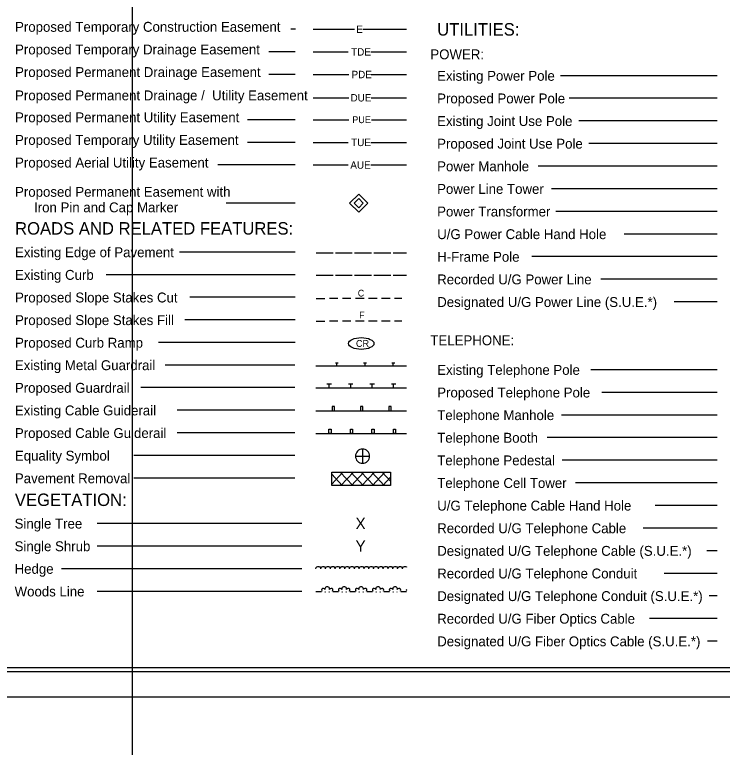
# Model space of a CAD drawing. Extents: x 572269 to 579912, y -56875 to -49627.
# Drawn here: x 574480 to 575106, y -52186 to -51539 of the extents above; entities that cross this region are included whole.
import ezdxf

# ---------------------------------------------------------------- set-up
doc = ezdxf.new("R2010")
doc.units = 0
for name, color, linetype in [('Default', 7, 'Continuous'), ('Prop Easement Permanent Drainage Utility', 7, 'Continuous'), ('Prop VPI Label', 7, 'Continuous'), ('Scratch_Level_3', 7, 'Continuous'), ('Sheet Cutting Line CELL', 7, 'Continuous'), ('Sheet Plot Border Inside CELL', 7, 'Continuous'), ('Sheet Plot Border Outside CELL', 7, 'Continuous'), ('Sheet Symbology CELL', 7, 'Continuous')]:
    doc.layers.add(name, color=color, linetype=linetype)

# ---------------------------------------------------------------- blocks, each defined once
blk = doc.blocks.new('EQCIR')
at = {"layer": 'Sheet Symbology CELL'}
for p, q in [((-0.25, 0), (0, 0)), ((0, 0.25), (0, 0)), ((0, 0), (0, -0.25)), ((0, 0), (0.25, 0))]:
    blk.add_line(p, q, dxfattribs=at)
for start, end in [(89.9944, 179.9989), (359.9944, 89.9989), (179.9944, 269.9989), (269.9944, 359.9989)]:
    blk.add_arc((0, 0), 0.25, start, end, dxfattribs=at)
blk = doc.blocks.new('ROW Marker Permanent Easement-E')
at = {"layer": 'Prop ROW Permanent Easement CELL'}
blk.add_line((0, 0), (0, 0), dxfattribs=at)
for points in [[(0, 0.072), (0.072, 0), (0, -0.072), (-0.072, 0)], [(0, 0.036), (0.036, 0), (0, -0.036), (-0.036, 0)]]:
    blk.add_lwpolyline(points, close=True, dxfattribs=at)
blk = doc.blocks.new('CR')
at = {"layer": 'Prop WCC CELL'}
blk.add_ellipse((0.02, -0.02), major_axis=(5.61, 0), ratio=0.462467, dxfattribs=at)
blk.add_text('CR', height=3, dxfattribs=at).set_placement((-2.34, -1.5))
blk = doc.blocks.new('PLAN SHEET SYMBOLOGY')
at = {"layer": 'Prop Easement Permanent Drainage Utility'}
for p, q in [((16.51, 10.596), (17.136, 10.596)), ((17.536, 10.596), (18.16, 10.596))]:
    blk.add_line(p, q, dxfattribs=at)
at = {"layer": 'Sheet Cutting Line CELL'}
blk.add_line((0, 0), (33.68, 0), dxfattribs=at)
at = {"layer": 'Sheet Plot Border Inside CELL'}
blk.add_lwpolyline([(0.26, 0.449), (33.59, 0.449), (33.59, 21.551), (0.26, 21.551)], close=True, dxfattribs=at)
at = {"layer": 'Sheet Plot Border Outside CELL'}
blk.add_lwpolyline([(0, 0), (33.68, 0), (33.68, 22), (0, 22)], close=True, dxfattribs=at)
at = {"layer": 'Sheet Symbology CELL'}
for p, q in [((16.197, 11.807), (16.114, 11.807)), ((16.51, 11.807), (16.562, 11.807)), ((16.562, 11.807), (17.237, 11.807)), ((17.387, 11.807), (18.062, 11.807)), ((18.062, 11.807), (18.16, 11.807)), ((16.189, 11.407), (15.726, 11.407)), ((16.51, 11.407), (16.577, 11.407)), ((16.577, 11.407), (17.127, 11.407)), ((17.527, 11.407), (18.077, 11.407)), ((18.077, 11.407), (18.16, 11.407)), ((16.189, 11.007), (15.726, 11.007)), ((16.51, 11.007), (16.586, 11.007)), ((16.586, 11.007), (17.136, 11.007)), ((17.536, 11.007), (18.086, 11.007)), ((18.086, 11.007), (18.16, 11.007)), ((23.656, 10.986), (20.882, 10.986)), ((23.656, 10.586), (21.038, 10.586)), ((16.189, 10.207), (15.347, 10.207)), ((16.51, 10.207), (16.587, 10.207)), ((16.587, 10.207), (17.137, 10.207)), ((17.537, 10.207), (18.087, 10.207)), ((18.087, 10.207), (18.16, 10.207)), ((23.656, 10.186), (21.206, 10.186)), ((16.189, 9.807), (15.347, 9.807)), ((16.51, 9.807), (16.577, 9.807)), ((16.577, 9.807), (17.127, 9.807)), ((17.527, 9.807), (18.077, 9.807)), ((18.077, 9.807), (18.16, 9.807)), ((23.656, 9.786), (21.386, 9.786)), ((16.189, 9.407), (14.82, 9.407)), ((16.51, 9.407), (16.577, 9.407)), ((16.577, 9.407), (17.127, 9.407)), ((17.527, 9.407), (18.077, 9.407)), ((18.077, 9.407), (18.16, 9.407)), ((23.656, 9.386), (20.486, 9.386)), ((23.656, 8.986), (20.726, 8.986)), ((16.189, 8.731), (14.969, 8.731)), ((23.656, 8.586), (20.798, 8.586)), ((23.656, 8.186), (22.009, 8.186)), ((16.189, 7.867), (14.142, 7.867)), ((16.56, 7.856), (16.86, 7.856)), ((16.9, 7.856), (17.2, 7.856)), ((17.24, 7.856), (17.54, 7.856)), ((17.58, 7.856), (17.88, 7.856)), ((17.92, 7.856), (18.16, 7.856)), ((23.656, 7.786), (20.378, 7.786)), ((16.189, 7.467), (12.846, 7.467)), ((16.56, 7.456), (16.86, 7.456)), ((16.9, 7.456), (17.2, 7.456)), ((17.24, 7.456), (17.54, 7.456)), ((17.58, 7.456), (17.88, 7.456)), ((17.92, 7.456), (18.16, 7.456)), ((23.656, 7.386), (21.597, 7.386)), ((16.189, 7.067), (14.326, 7.067)), ((16.56, 7.046), (16.712, 7.046)), ((16.946, 7.046), (16.795, 7.046)), ((17.176, 7.046), (17.024, 7.046)), ((17.411, 7.046), (17.255, 7.046)), ((17.64, 7.046), (17.485, 7.046)), ((17.871, 7.046), (17.714, 7.046)), ((18.077, 7.046), (17.949, 7.046)), ((23.656, 6.986), (22.892, 6.986)), ((16.189, 6.667), (14.235, 6.667)), ((16.56, 6.646), (16.712, 6.646)), ((16.946, 6.646), (16.795, 6.646)), ((17.176, 6.646), (17.024, 6.646)), ((17.411, 6.646), (17.255, 6.646)), ((17.64, 6.646), (17.485, 6.646)), ((17.871, 6.646), (17.714, 6.646)), ((18.077, 6.646), (17.949, 6.646)), ((16.189, 6.267), (13.771, 6.267)), ((16.186, 5.87), (13.889, 5.87)), ((16.557, 5.858), (18.157, 5.858)), ((16.9, 5.908), (16.95, 5.908)), ((16.925, 5.858), (16.925, 5.908)), ((17.4, 5.908), (17.45, 5.908)), ((17.425, 5.858), (17.425, 5.908)), ((17.9, 5.908), (17.95, 5.908)), ((17.925, 5.858), (17.925, 5.908)), ((23.656, 5.786), (21.418, 5.786)), ((16.186, 5.47), (13.461, 5.47)), ((18.157, 5.458), (16.557, 5.458)), ((16.751, 5.537), (16.831, 5.537)), ((16.791, 5.458), (16.791, 5.537)), ((17.131, 5.537), (17.211, 5.537)), ((17.171, 5.458), (17.171, 5.537)), ((17.511, 5.537), (17.591, 5.537)), ((17.551, 5.458), (17.551, 5.537)), ((17.891, 5.537), (17.971, 5.537)), ((17.931, 5.458), (17.931, 5.537)), ((23.656, 5.386), (21.615, 5.386)), ((16.186, 5.07), (14.1, 5.07)), ((16.557, 5.058), (18.157, 5.058)), ((23.656, 4.986), (20.899, 4.986)), ((16.186, 4.67), (14.1, 4.67)), ((16.557, 4.658), (18.157, 4.658)), ((23.656, 4.586), (20.646, 4.586)), ((16.186, 4.27), (13.334, 4.27)), ((23.656, 4.186), (20.913, 4.186)), ((16.836, 3.976), (17.878, 3.976)), ((16.836, 3.742), (16.836, 3.976)), ((16.836, 3.964), (16.847, 3.976)), ((16.836, 3.765), (17.033, 3.976)), ((17.021, 3.742), (16.836, 3.94)), ((17.207, 3.742), (16.987, 3.976)), ((16.999, 3.742), (17.219, 3.976)), ((17.392, 3.742), (17.173, 3.976)), ((17.184, 3.742), (17.405, 3.976)), ((17.578, 3.742), (17.358, 3.976)), ((17.37, 3.742), (17.59, 3.976)), ((17.764, 3.742), (17.543, 3.976)), ((17.556, 3.742), (17.775, 3.976)), ((17.878, 3.817), (17.729, 3.976)), ((17.741, 3.742), (17.878, 3.888)), ((17.878, 3.976), (17.878, 3.742)), ((16.186, 3.87), (13.334, 3.87)), ((23.656, 3.786), (21.151, 3.786)), ((17.878, 3.742), (16.836, 3.742)), ((23.656, 3.386), (22.555, 3.386)), ((16.309, 3.068), (12.686, 3.068)), ((23.656, 2.986), (22.345, 2.986)), ((16.309, 2.668), (12.686, 2.668)), ((23.656, 2.586), (23.473, 2.586)), ((16.309, 2.268), (12.055, 2.268)), ((16.557, 2.268), (16.563, 2.287)), ((16.563, 2.287), (16.575, 2.3)), ((16.575, 2.3), (16.591, 2.309)), ((16.591, 2.309), (16.61, 2.309)), ((16.61, 2.309), (16.626, 2.299)), ((16.626, 2.299), (16.637, 2.286)), ((16.637, 2.286), (16.641, 2.269)), ((16.642, 2.268), (16.648, 2.287)), ((16.648, 2.287), (16.66, 2.3)), ((16.66, 2.3), (16.676, 2.309)), ((16.676, 2.309), (16.695, 2.309)), ((16.695, 2.309), (16.711, 2.299)), ((16.711, 2.299), (16.722, 2.286)), ((16.722, 2.286), (16.726, 2.269)), ((16.727, 2.268), (16.733, 2.287)), ((16.733, 2.287), (16.745, 2.3)), ((16.745, 2.3), (16.761, 2.309)), ((16.761, 2.309), (16.78, 2.309)), ((16.78, 2.309), (16.796, 2.299)), ((16.796, 2.299), (16.807, 2.286)), ((16.807, 2.286), (16.811, 2.269)), ((16.812, 2.268), (16.818, 2.287)), ((16.818, 2.287), (16.83, 2.3)), ((16.83, 2.3), (16.846, 2.309)), ((16.846, 2.309), (16.865, 2.309)), ((16.865, 2.309), (16.881, 2.299)), ((16.881, 2.299), (16.892, 2.286)), ((16.892, 2.286), (16.896, 2.269)), ((16.897, 2.268), (16.903, 2.287)), ((16.903, 2.287), (16.915, 2.3)), ((16.915, 2.3), (16.931, 2.309)), ((16.931, 2.309), (16.95, 2.309)), ((16.95, 2.309), (16.966, 2.299)), ((16.966, 2.299), (16.977, 2.286)), ((16.977, 2.286), (16.981, 2.269)), ((16.982, 2.268), (16.988, 2.287)), ((16.988, 2.287), (17, 2.3)), ((17, 2.3), (17.016, 2.309)), ((17.016, 2.309), (17.035, 2.309)), ((17.035, 2.309), (17.051, 2.299)), ((17.051, 2.299), (17.062, 2.286)), ((17.062, 2.286), (17.066, 2.269)), ((17.067, 2.268), (17.073, 2.287)), ((17.073, 2.287), (17.085, 2.3)), ((17.085, 2.3), (17.101, 2.309)), ((17.101, 2.309), (17.12, 2.309)), ((17.12, 2.309), (17.136, 2.299)), ((17.136, 2.299), (17.147, 2.286)), ((17.147, 2.286), (17.151, 2.269)), ((17.152, 2.268), (17.158, 2.287)), ((17.158, 2.287), (17.17, 2.3)), ((17.17, 2.3), (17.186, 2.309)), ((17.186, 2.309), (17.205, 2.309)), ((17.205, 2.309), (17.221, 2.299)), ((17.221, 2.299), (17.232, 2.286)), ((17.232, 2.286), (17.236, 2.269)), ((17.237, 2.268), (17.243, 2.287)), ((17.243, 2.287), (17.255, 2.3)), ((17.255, 2.3), (17.271, 2.309)), ((17.271, 2.309), (17.29, 2.309)), ((17.29, 2.309), (17.306, 2.299)), ((17.306, 2.299), (17.317, 2.286)), ((17.317, 2.286), (17.321, 2.269)), ((17.322, 2.268), (17.328, 2.287)), ((17.328, 2.287), (17.34, 2.3)), ((17.34, 2.3), (17.356, 2.309)), ((17.356, 2.309), (17.375, 2.309)), ((17.375, 2.309), (17.391, 2.299)), ((17.391, 2.299), (17.402, 2.286)), ((17.402, 2.286), (17.406, 2.269)), ((17.407, 2.268), (17.413, 2.287)), ((17.413, 2.287), (17.425, 2.3)), ((17.425, 2.3), (17.441, 2.309)), ((17.441, 2.309), (17.46, 2.309)), ((17.46, 2.309), (17.476, 2.299)), ((17.476, 2.299), (17.487, 2.286)), ((17.487, 2.286), (17.491, 2.269)), ((17.492, 2.268), (17.498, 2.287)), ((17.498, 2.287), (17.51, 2.3)), ((17.51, 2.3), (17.526, 2.309)), ((17.526, 2.309), (17.545, 2.309)), ((17.545, 2.309), (17.561, 2.299)), ((17.561, 2.299), (17.572, 2.286)), ((17.572, 2.286), (17.576, 2.269)), ((17.577, 2.268), (17.583, 2.287)), ((17.583, 2.287), (17.595, 2.3)), ((17.595, 2.3), (17.611, 2.309)), ((17.611, 2.309), (17.63, 2.309)), ((17.63, 2.309), (17.646, 2.299)), ((17.646, 2.299), (17.657, 2.286)), ((17.657, 2.286), (17.661, 2.269)), ((17.662, 2.268), (17.668, 2.287)), ((17.668, 2.287), (17.68, 2.3)), ((17.68, 2.3), (17.696, 2.309)), ((17.696, 2.309), (17.715, 2.309)), ((17.715, 2.309), (17.731, 2.299)), ((17.731, 2.299), (17.742, 2.286)), ((17.742, 2.286), (17.746, 2.269)), ((17.747, 2.268), (17.753, 2.287)), ((17.753, 2.287), (17.765, 2.3)), ((17.765, 2.3), (17.781, 2.309)), ((17.781, 2.309), (17.8, 2.309)), ((17.8, 2.309), (17.816, 2.299)), ((17.816, 2.299), (17.827, 2.286)), ((17.827, 2.286), (17.831, 2.269)), ((17.832, 2.268), (17.838, 2.287)), ((17.838, 2.287), (17.85, 2.3)), ((17.85, 2.3), (17.866, 2.309)), ((17.866, 2.309), (17.885, 2.309)), ((17.885, 2.309), (17.901, 2.299)), ((17.901, 2.299), (17.912, 2.286)), ((17.912, 2.286), (17.916, 2.269)), ((17.917, 2.268), (17.923, 2.287)), ((17.923, 2.287), (17.935, 2.3)), ((17.935, 2.3), (17.951, 2.309)), ((17.951, 2.309), (17.97, 2.309)), ((17.97, 2.309), (17.986, 2.299)), ((17.986, 2.299), (17.997, 2.286)), ((17.997, 2.286), (18.001, 2.269)), ((18.002, 2.268), (18.008, 2.287)), ((18.008, 2.287), (18.02, 2.3)), ((18.02, 2.3), (18.036, 2.309)), ((18.036, 2.309), (18.055, 2.309)), ((18.055, 2.309), (18.071, 2.299)), ((18.071, 2.299), (18.082, 2.286)), ((18.082, 2.286), (18.086, 2.269)), ((18.087, 2.268), (18.093, 2.287)), ((18.093, 2.287), (18.105, 2.3)), ((18.105, 2.3), (18.121, 2.309)), ((18.121, 2.309), (18.14, 2.309)), ((18.14, 2.309), (18.156, 2.299)), ((18.156, 2.299), (18.157, 2.298)), ((23.656, 2.186), (22.717, 2.186)), ((16.309, 1.868), (12.686, 1.868)), ((16.557, 1.868), (16.657, 1.868)), ((16.716, 1.858), (16.726, 1.858)), ((16.786, 1.858), (16.796, 1.858)), ((16.857, 1.868), (16.957, 1.868)), ((17.016, 1.858), (17.026, 1.858)), ((17.086, 1.858), (17.096, 1.858)), ((17.157, 1.868), (17.257, 1.868)), ((17.316, 1.858), (17.326, 1.858)), ((17.386, 1.858), (17.396, 1.858)), ((17.457, 1.868), (17.557, 1.868)), ((17.616, 1.858), (17.626, 1.858)), ((17.686, 1.858), (17.696, 1.858)), ((17.757, 1.868), (17.857, 1.868)), ((17.916, 1.858), (17.926, 1.858)), ((17.986, 1.858), (17.996, 1.858)), ((18.057, 1.868), (18.157, 1.868)), ((23.656, 1.786), (23.515, 1.786)), ((23.656, 1.386), (22.455, 1.386)), ((23.656, 0.986), (23.485, 0.986))]:
    blk.add_line(p, q, dxfattribs=at)
for points in [[(33.34, 21.5), (3.34, 21.5), (3.34, 0.52), (33.34, 0.52)], [(16.846, 5.058), (16.886, 5.058), (16.886, 5.138), (16.846, 5.138)], [(17.346, 5.058), (17.386, 5.058), (17.386, 5.138), (17.346, 5.138)], [(17.846, 5.058), (17.886, 5.058), (17.886, 5.138), (17.846, 5.138)], [(16.786, 4.738), (16.826, 4.738), (16.826, 4.658), (16.786, 4.658)], [(17.166, 4.738), (17.206, 4.738), (17.206, 4.658), (17.166, 4.658)], [(17.546, 4.738), (17.586, 4.738), (17.586, 4.658), (17.546, 4.658)], [(17.926, 4.738), (17.966, 4.738), (17.966, 4.658), (17.926, 4.658)]]:
    blk.add_lwpolyline(points, close=True, dxfattribs=at)
for centre, radius, start, end in [((16.756, 1.909), 0.0412, 345.9638, 194.0362), ((17.056, 1.909), 0.0412, 345.9638, 194.0362), ((17.356, 1.909), 0.0412, 345.9638, 194.0362), ((17.656, 1.909), 0.0412, 345.9638, 194.0362), ((17.956, 1.909), 0.0412, 345.9638, 194.0362), ((16.686, 1.889), 0.0316, 18.435, 219.2315), ((16.826, 1.889), 0.0316, 320.7685, 161.5651), ((16.986, 1.889), 0.0316, 18.435, 219.2315), ((17.126, 1.889), 0.0316, 320.7685, 161.5651), ((17.286, 1.889), 0.0316, 18.435, 219.2315), ((17.426, 1.889), 0.0316, 320.7685, 161.5651), ((17.586, 1.889), 0.0316, 18.435, 219.2315), ((17.726, 1.889), 0.0316, 320.7685, 161.5651), ((17.886, 1.889), 0.0316, 18.435, 219.2315), ((18.026, 1.889), 0.0316, 320.7685, 161.5651), ((18.186, 1.889), 0.0316, 156.251, 203.749)]:
    blk.add_arc(centre, radius, start, end, dxfattribs=at)
at = {"layer": 'Default', "xscale": 0.5, "yscale": 0.5}
blk.add_blockref('EQCIR', (17.381, 4.258), dxfattribs=at)
at = {"layer": 'Sheet Symbology CELL'}
for name, p, xscale, yscale in [('ROW Marker Permanent Easement-E', (17.313, 8.731), 2.2367546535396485, 2.2367546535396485), ('CR', (17.358, 6.251), 0.04, 0.04)]:
    blk.add_blockref(name, p, dxfattribs=dict(at, xscale=xscale, yscale=yscale))
at = {"layer": 'Prop Easement Permanent Drainage Utility'}
blk.add_text('DUE', height=0.131, dxfattribs=at).set_placement((17.168, 10.53))
at = {"layer": 'Sheet Symbology CELL'}
for s, height, p in [('Proposed Temporary Construction Easement', 0.175, (11.234, 11.762)), ('E', 0.131, (17.269, 11.741)), ('UTILITIES:', 0.22, (18.701, 11.695)), ('Proposed Temporary Drainage Easement', 0.175, (11.234, 11.362)), ('TDE', 0.131, (17.179, 11.341)), ('POWER:', 0.175, (18.581, 11.276)), ('Proposed Permanent Drainage Easement', 0.175, (11.234, 10.962)), ('PDE', 0.131, (17.186, 10.941)), ('Existing Power Pole', 0.175, (18.701, 10.896)), ('Proposed Permanent Drainage /  Utility Easement', 0.175, (11.234, 10.55)), ('Proposed Power Pole', 0.175, (18.701, 10.496)), ('Proposed Permanent Utility Easement', 0.175, (11.234, 10.162)), ('PUE', 0.12, (17.199, 10.147)), ('Existing Joint Use Pole', 0.175, (18.701, 10.096)), ('Proposed Temporary Utility Easement', 0.175, (11.234, 9.762)), ('TUE', 0.131, (17.179, 9.741)), ('Proposed Joint Use Pole', 0.175, (18.701, 9.696)), ('Proposed Aerial Utility Easement', 0.175, (11.234, 9.362)), ('AUE', 0.131, (17.165, 9.341)), ('Power Manhole', 0.175, (18.701, 9.296)), ('Power Line Tower', 0.175, (18.701, 8.896)), ('Proposed Permanent Easement with', 0.175, (11.234, 8.845)), ('Iron Pin and Cap Marker', 0.175, (11.57, 8.57)), ('Power Transformer', 0.175, (18.701, 8.496)), ('ROADS AND RELATED FEATURES:', 0.22, (11.234, 8.176)), ('U/G Power Cable Hand Hole', 0.175, (18.702, 8.096)), ('Existing Edge of Pavement', 0.175, (11.234, 7.776)), ('H-Frame Pole', 0.175, (18.702, 7.696)), ('Existing Curb', 0.175, (11.234, 7.376)), ('Recorded U/G Power Line', 0.175, (18.702, 7.296)), ('Proposed Slope Stakes Cut', 0.175, (11.234, 6.976)), ('C', 0.119, (17.296, 7.081)), ('Designated U/G Power Line (S.U.E.*)', 0.175, (18.702, 6.896)), ('Proposed Slope Stakes Fill', 0.175, (11.234, 6.576)), ('F', 0.119, (17.32, 6.694)), ('Proposed Curb Ramp', 0.175, (11.234, 6.176)), ('TELEPHONE:', 0.175, (18.581, 6.219)), ('Existing Metal Guardrail', 0.175, (11.231, 5.779)), ('Existing Telephone Pole', 0.175, (18.702, 5.696)), ('Proposed Guardrail', 0.175, (11.231, 5.379)), ('Proposed Telephone Pole', 0.175, (18.702, 5.296)), ('Existing Cable Guiderail', 0.175, (11.231, 4.979)), ('Telephone Manhole', 0.175, (18.702, 4.896)), ('Proposed Cable Guiderail', 0.175, (11.231, 4.579)), ('Telephone Booth', 0.175, (18.702, 4.496)), ('Equality Symbol', 0.175, (11.231, 4.179)), ('Telephone Pedestal', 0.175, (18.702, 4.096)), ('Pavement Removal', 0.175, (11.231, 3.779)), ('Telephone Cell Tower', 0.175, (18.702, 3.696)), ('VEGETATION:', 0.22, (11.231, 3.377)), ('U/G Telephone Cable Hand Hole', 0.175, (18.702, 3.296)), ('Single Tree', 0.175, (11.226, 2.978)), ('X', 0.2, (17.257, 2.968)), ('Recorded U/G Telephone Cable', 0.175, (18.702, 2.896)), ('Single Shrub', 0.175, (11.226, 2.578)), ('Y', 0.2, (17.257, 2.568)), ('Designated U/G Telephone Cable (S.U.E.*)', 0.175, (18.702, 2.496)), ('Hedge', 0.175, (11.226, 2.178)), ('Recorded U/G Telephone Conduit', 0.175, (18.702, 2.096)), ('Woods Line', 0.175, (11.226, 1.778)), ('Designated U/G Telephone Conduit (S.U.E.*)', 0.175, (18.702, 1.696)), ('Recorded U/G Fiber Optics Cable', 0.175, (18.702, 1.296)), ('Designated U/G Fiber Optics Cable (S.U.E.*)', 0.175, (18.702, 0.896))]:
    blk.add_text(s, height=height, dxfattribs=at).set_placement(p)

msp = doc.modelspace()

# ---------------------------------------------------------------- linework, layer by layer
at = {"layer": 'Scratch_Level_3'}
msp.add_line((574584.69, -56875.35), (574584.69, -49627.25), dxfattribs=at)

# ---------------------------------------------------------------- block references
at = {"layer": 'Prop VPI Label', "xscale": 50, "yscale": 50}
msp.add_blockref('PLAN SHEET SYMBOLOGY', (573919.14, -52141.96), dxfattribs=at)

doc.saveas('drawing.dxf')
